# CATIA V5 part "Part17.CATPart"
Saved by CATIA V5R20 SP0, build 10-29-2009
Part number: 9AE031620-2
Revision: ANY
Definition: UNKNOWN
Nomenclature: 9AE031620-2
Source: Unknown
Bounding box of the stored display mesh (mm): x -11 to 11, y -10.833 to 10.833, z 0 to 32
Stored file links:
  C:\Users\Utente\Desktop\IO LAVORO\3D X SITO CF\CUMSA\3D files AE\AE 041620\Part17.CATPart
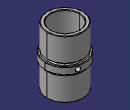
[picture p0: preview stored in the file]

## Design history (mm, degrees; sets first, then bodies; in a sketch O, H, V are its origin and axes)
Body1 "Cortar-Extruir2" (main body)
  Solid1: solid without history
